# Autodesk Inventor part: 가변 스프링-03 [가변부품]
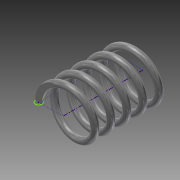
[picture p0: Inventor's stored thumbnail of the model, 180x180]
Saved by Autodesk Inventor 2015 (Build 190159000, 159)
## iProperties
Created: 2015-05
Part Number: 가변 스프링-03 [가변부품]
Material: 강철, 탄소
Document SubType Name: Modeling
Designer: Young-Hwan
Density: 7.85 g/cm^3
Appearance: 반연마
Mass: 18.8381 g
Surface Area: 32.5478 cm^2
Volume: 2.39976 cm^3
Author: Young-Hwan
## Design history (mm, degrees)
sketch "스케치1"
  geometry: L1 (0, 0)-(-11, 0); L2 (-11, 0)-(-11, 36.411); L3 (-11, 36.411)-(0, 36.411); L4 (0, 36.411)-(0, 0); C1 r 1.5 at (-11, 0)
  constraints: 8 end point, 2 parallel, 1 centre point, 1 coincident, 1 horizontal, 1 perpendicular
  dimensions: "d0" = 22 diameter of L2 L4; "d1" = 36.4112 distance between parallel lines of L3 L1 (derived); "d2" = 3 diameter of C1 (derived)
feature "코일1" sketch "스케치1" pitch "d3" = 10; turns "d5" = 5; dims "d4" = 36.4112 (= d1), "d6" = 0, angle "d7" = 90 deg, angle "d8" = 90 deg, "d9" = 0, "d10" = 0
sketch "스케치2"
  geometry: L1 (12.5, 0)-(9.5, 0) reference; 1 further point
  constraints: 1 horizontal alignment
extrude "돌출1" cut sketch "스케치2" stored distance "d11" = 10; taper "d12" = 0 deg
node "작업 평면1"
sketch "스케치3"
  geometry: L1 (-1.5, 0)-(1.5, 0) reference; 1 further point
  constraints: 1 horizontal alignment
extrude "돌출2" cut sketch "스케치3" stored distance "d14" = 10; taper "d15" = 0 deg
node "솔리드1"
node "절단 모서리 투영1"
node "절단 모서리 투영2"
other parameters: "d13" = 90 deg
